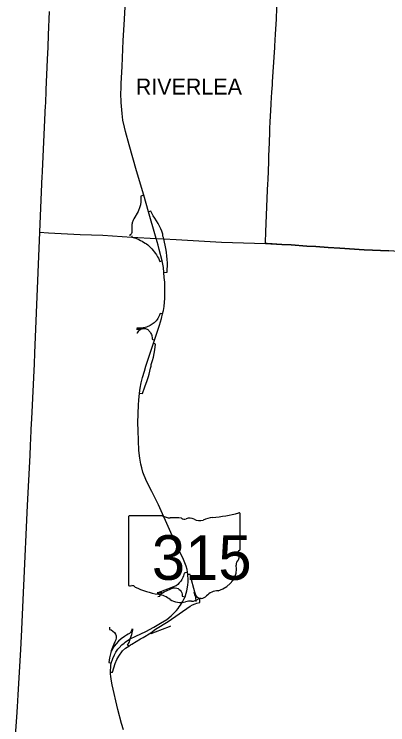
# Model space of a CAD drawing. Extents: x -1146 to -445, y -1283 to -822.
# Drawn here: x -916.9 to -887.8, y -1003.9 to -948.5 of the extents above; entities that cross this region are included whole.
import ezdxf

# ---------------------------------------------------------------- set-up
doc = ezdxf.new("R2010")
doc.units = 0
for name, color, linetype in [('GM_X_Corporation_Text', 7, 'Continuous'), ('GM_X_Interchange_Ramps', 7, 'Continuous'), ('GM_X_State_Route', 7, 'Continuous'), ('GM_X_State_Shield', 7, 'Continuous'), ('GM_X_Township', 7, 'Continuous'), ('GM_X_US_Route', 7, 'Continuous')]:
    doc.layers.add(name, color=color, linetype=linetype)

msp = doc.modelspace()

# ---------------------------------------------------------------- linework, layer by layer
at = {"layer": 'GM_X_Interchange_Ramps'}
for points in [[(-906.827, -962.643), (-907.057, -962.709), (-907.047, -962.892), (-907.043, -962.958), (-907.042, -963.03), (-907.044, -963.109), (-907.049, -963.185), (-907.056, -963.249), (-907.067, -963.323), (-907.081, -963.396), (-907.099, -963.472), (-907.117, -963.537), (-907.144, -963.62), (-907.171, -963.69), (-907.198, -963.753), (-907.233, -963.826), (-907.27, -963.896), (-907.59, -964.473), (-907.625, -964.533), (-907.656, -964.595), (-907.681, -964.654), (-907.702, -964.714), (-907.722, -964.785), (-907.737, -964.856), (-907.745, -964.913), (-907.75, -964.957), (-907.752, -964.999), (-907.761, -965.439), (-907.764, -965.536), (-907.774, -965.615), (-907.793, -965.658), (-907.83, -965.7), (-907.906, -965.731), (-907.906, -965.804)], [(-905.332, -965.842), (-905.345, -965.666), (-905.412, -965.454), (-905.487, -965.272), (-905.586, -965.06), (-905.707, -964.842), (-905.959, -964.428), (-906.082, -964.234), (-906.267, -963.893), (-906.453, -963.946)], [(-907.753, -965.807), (-907.753, -965.913), (-907.537, -965.966), (-907.447, -965.995), (-907.333, -966.038), (-907.204, -966.093), (-907.064, -966.16), (-906.95, -966.221), (-906.833, -966.291), (-906.714, -966.369), (-906.612, -966.442), (-906.516, -966.517), (-906.411, -966.607), (-906.3, -966.71), (-906.194, -966.819), (-906.09, -966.937), (-906, -967.05), (-905.904, -967.184), (-905.829, -967.3), (-905.745, -967.444), (-905.686, -967.557), (-905.575, -967.796), (-905.382, -967.753)], [(-905.258, -968.657), (-905.006, -968.637), (-904.987, -967.927), (-904.993, -967.623), (-905.014, -967.387), (-905.061, -967.077), (-905.106, -966.795), (-905.272, -966.05), (-905.297, -965.946), (-905.332, -965.842)], [(-905.359, -971.899), (-905.55, -971.859), (-905.61, -972.002), (-905.647, -972.083), (-905.685, -972.158), (-905.73, -972.242), (-905.776, -972.318), (-905.863, -972.442), (-905.943, -972.523), (-906.008, -972.581), (-906.084, -972.643), (-906.16, -972.698), (-906.245, -972.753), (-906.333, -972.802), (-906.42, -972.845), (-906.516, -972.885), (-906.615, -972.92), (-906.711, -972.948), (-906.812, -972.971), (-906.873, -972.977), (-906.972, -972.992), (-907.091, -973), (-907.215, -973.008), (-907.345, -973.01), (-907.398, -973.031)], [(-907.394, -973.085), (-907.318, -973.085), (-907.129, -973.076), (-906.942, -973.027), (-906.937, -973.045)], [(-907.362, -973.37), (-907.3, -973.367), (-907.254, -973.277), (-907.213, -973.219), (-907.164, -973.167), (-907.111, -973.124), (-907.059, -973.092), (-906.988, -973.059), (-906.937, -973.045), (-906.913, -973.038), (-906.843, -973.028), (-906.776, -973.028), (-906.695, -973.038), (-906.624, -973.059), (-906.566, -973.085), (-906.515, -973.115), (-906.465, -973.152), (-906.428, -973.187), (-906.394, -973.225), (-906.347, -973.283), (-906.302, -973.348), (-906.261, -973.422), (-906.232, -973.485), (-906.206, -973.564), (-906.188, -973.638), (-906.177, -973.724), (-906.172, -973.868), (-905.983, -973.933)], [(-906.256, -975.974), (-906.234, -975.826), (-906.139, -975.535), (-906.068, -975.262), (-906.007, -974.972), (-905.967, -974.687), (-905.897, -974.242), (-906.069, -974.183)], [(-907.155, -978.066), (-906.922, -978.104), (-906.731, -977.581), (-906.555, -977.082), (-906.446, -976.773), (-906.408, -976.597), (-906.289, -976.112), (-906.256, -975.974)], [(-903.407, -992.018), (-903.672, -992.114), (-903.719, -992.301), (-903.774, -992.449), (-903.852, -992.598), (-903.938, -992.723), (-904.054, -992.866), (-904.17, -992.979), (-904.312, -993.078), (-904.467, -993.143), (-904.628, -993.218), (-905.725, -993.625), (-905.79, -993.639)], [(-902.452, -994.306), (-902.453, -994.139), (-902.544, -994.078), (-902.641, -994.001), (-902.725, -993.895), (-902.763, -993.806), (-902.84, -993.575), (-902.914, -993.296), (-903.112, -992.611), (-903.215, -992.206), (-903.388, -992.21)], [(-905.771, -993.716), (-905.701, -993.693), (-905.391, -993.582), (-905.376, -993.636)], [(-905.734, -993.917), (-905.583, -993.901), (-905.543, -993.808), (-905.509, -993.759), (-905.44, -993.677), (-905.376, -993.636), (-905.239, -993.569), (-904.524, -993.258), (-904.377, -993.249), (-904.253, -993.272), (-904.154, -993.303), (-904.06, -993.365), (-903.991, -993.425), (-903.915, -993.527), (-903.853, -993.644), (-903.828, -993.74), (-903.825, -993.866), (-903.831, -993.897), (-903.611, -993.947)], [(-902.754, -994.32), (-902.755, -994.2), (-902.766, -994.081), (-902.78, -993.968), (-902.812, -993.863), (-902.899, -993.594), (-902.84, -993.575)], [(-909.416, -999.818), (-909.252, -999.819), (-909.043, -999.133), (-908.911, -998.824), (-908.765, -998.571), (-908.467, -998.159), (-908.254, -997.962), (-907.993, -997.784), (-907.856, -997.691), (-907.748, -997.626), (-907.079, -997.225), (-906.877, -997.115), (-906.285, -996.742), (-905.897, -996.479), (-904.922, -995.871), (-903.216, -994.684), (-903.023, -994.574), (-902.829, -994.486), (-902.691, -994.442), (-902.451, -994.393), (-902.452, -994.306)], [(-909.48, -996.311), (-909.486, -996.486), (-909.371, -996.525), (-909.23, -996.619), (-909.108, -996.73), (-909.035, -996.846), (-908.982, -996.99), (-908.984, -997.149), (-909.009, -997.298), (-909.071, -997.456), (-909.153, -997.638), (-909.254, -997.9), (-909.362, -998.16), (-909.399, -998.292), (-909.42, -998.388), (-909.485, -998.709), (-909.529, -999.067), (-909.35, -999.127)], [(-907.762, -996.436), (-907.756, -996.533), (-907.794, -996.649), (-907.851, -996.733), (-907.924, -996.799), (-908.036, -996.869), (-908.161, -996.946), (-908.323, -997.039), (-908.581, -997.222), (-908.795, -997.409), (-908.983, -997.61), (-909.126, -997.797), (-909.234, -997.976), (-909.329, -998.176), (-909.362, -998.16)], [(-907.993, -997.784), (-908.086, -997.706), (-907.968, -997.507), (-907.872, -997.232), (-907.748, -996.873), (-907.663, -996.521), (-907.669, -996.441)], [(-906.285, -996.742), (-906.25, -996.818), (-905.899, -996.666), (-904.817, -996.26), (-904.704, -996.206)]]:
    msp.add_lwpolyline(points, dxfattribs=at)
at = {"layer": 'GM_X_State_Route'}
for points in [[(-908.513, -952.597), (-908.427, -950.591), (-908.354, -949.36), (-908.249, -947.514), (-908.22, -946.809)], [(-908.584, -954.308), (-908.57, -953.942), (-908.513, -952.597)], [(-908.475, -956.542), (-908.513, -956.277), (-908.57, -955.418), (-908.599, -954.687), (-908.584, -954.308)], [(-905.9, -965.843), (-906.453, -963.946), (-906.827, -962.643), (-907.378, -960.731), (-907.964, -958.723), (-908.241, -957.667), (-908.327, -957.323), (-908.441, -956.778), (-908.475, -956.542)], [(-905.705, -966.546), (-905.851, -966.018), (-905.9, -965.843)], [(-908.412, -1004.323), (-908.549, -1003.819), (-908.852, -1002.72), (-909.284, -1000.82), (-909.362, -1000.362), (-909.399, -1000.129), (-909.409, -999.968), (-909.416, -999.818), (-909.409, -999.675), (-909.399, -999.453), (-909.376, -999.291), (-909.35, -999.127), (-909.233, -998.757), (-909.108, -998.476), (-908.986, -998.264), (-908.829, -998.026), (-908.738, -997.914), (-908.534, -997.701), (-908.361, -997.565), (-908.263, -997.487), (-908.079, -997.352), (-907.872, -997.232), (-907.433, -997.011), (-906.665, -996.649), (-906.044, -996.318), (-905.515, -996.013), (-905.026, -995.708), (-904.69, -995.42), (-904.424, -995.172), (-904.269, -995.005), (-904.138, -994.853), (-904.056, -994.728), (-903.954, -994.59), (-903.811, -994.344), (-903.701, -994.133), (-903.611, -993.947), (-903.52, -993.658), (-903.467, -993.493), (-903.414, -993.206), (-903.388, -993.021), (-903.373, -992.799), (-903.373, -992.546), (-903.384, -992.297), (-903.388, -992.21), (-903.407, -992.018), (-903.455, -991.82), (-903.529, -991.55), (-903.738, -991.033), (-904.033, -990.381), (-904.707, -988.942), (-905.685, -986.787), (-906.186, -985.748), (-906.599, -984.921), (-906.885, -984.232), (-906.985, -983.892), (-907.055, -983.605), (-907.132, -983.126), (-907.194, -982.53), (-907.264, -980.99), (-907.278, -980.382), (-907.231, -978.97), (-907.217, -978.604), (-907.155, -978.066), (-907.102, -977.681), (-907.026, -977.277), (-906.922, -976.849), (-906.774, -976.364), (-906.651, -975.959), (-906.069, -974.183), (-905.983, -973.933), (-905.592, -972.767), (-905.445, -972.24), (-905.359, -971.899), (-905.291, -971.633), (-905.232, -971.311), (-905.181, -970.671), (-905.175, -969.973), (-905.193, -969.428), (-905.225, -969.066), (-905.258, -968.657), (-905.289, -968.286), (-905.382, -967.753), (-905.614, -966.873), (-905.705, -966.546)]]:
    msp.add_lwpolyline(points, dxfattribs=at)
at = {"layer": 'GM_X_State_Shield'}
for p, q in [((-905.383, -987.622), (-907.932, -987.622)), ((-899.316, -990.254), (-899.316, -987.491)), ((-908.017, -987.712), (-908.017, -992.996)), ((-899.317, -990.254), (-899.316, -990.254))]:
    msp.add_line(p, q, dxfattribs=at)
for centre, major_axis, start_param, end_param in [((-907.917, -987.701), (0.101, 0), 1.712693, 3.28349), ((-904.777, -987.008), (0.978, 0), 4.042523, 4.731795), ((-902.416, -980.419), (9.227, 0), 4.814394, 5.042369), ((-899.413, -987.479), (0.0969, 0), 6.141152, 7.989035), ((-904.452, -990.588), (3.51, 0), 1.404758, 1.657858), ((-903.656, -987.674), (0.282, 0), 3.836095, 5.185415), ((-903.241, -988.284), (0.586, 0), 0.950623, 2.079405), ((-902.485, -987.447), (0.705, 0), 4.081561, 5.145723), ((-901.239, -989.235), (1.856, 0), 1.699011, 2.107814), ((-899.339, -990.457), (0.15, 0), 1.883978, 3.671073), ((-899.42, -990.265), (0.104, 0), 5.05454, 6.418171), ((-900.292, -990.807), (0.9, 0), 5.934695, 6.695948), ((-901.899, -991.762), (2.308, 0), 5.101752, 6.440018), ((-898.969, -991.411), (0.655, 0), 2.387724, 3.262537), ((-907.917, -993.007), (0.102, 0), 3.00124, 4.508301), ((-907.901, -992.467), (0.776, 0), 4.665946, 4.897461), ((-907.742, -993.3), (0.28, 0), 0.519207, 1.627899), ((-904.209, -988.554), (6.663, 0), 4.195997, 4.488961), ((-906.196, -995.369), (2.085, 0), 0.823519, 1.323587), ((-900.926, -994.479), (1.264, 0), 1.647645, 2.488434), ((-903.941, -993.327), (1.323, 0), 4.026481, 4.996735), ((-903.177, -995.153), (1.087, 0), 1.495662, 1.94098), ((-903.08, -993.722), (0.705, 0), 4.691044, 5.507374), ((-902.442, -994.234), (0.198, 0), 1.147584, 2.315152), ((-902.527, -993.508), (0.746, 0), 4.937069, 5.64225)]:
    msp.add_ellipse(centre, major_axis=major_axis, ratio=0.8, start_param=start_param, end_param=end_param, dxfattribs=at)
at = {"layer": 'GM_X_Township'}
for points in [[(-914.177, -948.328), (-914.254, -950.134), (-914.296, -951.093), (-914.336, -952.048), (-914.439, -954.432), (-914.484, -955.503), (-914.49, -955.625), (-914.517, -956.216), (-914.724, -960.765), (-914.741, -960.908), (-914.761, -961.127), (-914.943, -965.512), (-915.317, -974.951), (-915.358, -975.787), (-915.565, -980.074), (-915.604, -980.871), (-915.611, -981.008), (-915.666, -982.149), (-915.702, -982.896), (-915.895, -986.825), (-916.195, -993.062), (-916.363, -997.038), (-916.409, -998.056), (-916.635, -1001.582), (-916.691, -1002.532), (-916.732, -1003.331), (-916.907, -1005.839)], [(-914.943, -965.512), (-914.247, -965.562), (-911.762, -965.703), (-910, -965.75), (-907.753, -965.913), (-905.851, -966.018), (-905.272, -966.05), (-904.299, -966.104), (-900.782, -966.287), (-897.337, -966.391), (-896.065, -966.473), (-895.339, -966.52), (-894.117, -966.599), (-893.437, -966.643), (-892.459, -966.706), (-891.566, -966.763), (-889.657, -966.886), (-887.755, -966.987)]]:
    msp.add_lwpolyline(points, dxfattribs=at)
at = {"layer": 'GM_X_US_Route'}
for points in [[(-896.897, -955.529), (-896.894, -955.479), (-896.867, -955.024), (-896.842, -954.602), (-896.808, -954.026), (-896.797, -953.835), (-896.795, -953.8), (-896.746, -953.02), (-896.629, -951.135), (-896.621, -951.019), (-896.559, -950.089), (-896.481, -948.913), (-896.452, -948.041), (-896.428, -947.306), (-896.405, -946.579)], [(-897.212, -966.399), (-897.338, -966.391), (-897.341, -966.336), (-897.308, -965.496), (-897.183, -962.244), (-897.159, -961.755), (-897.147, -961.439), (-897.094, -960.027), (-897.078, -959.59), (-897.038, -958.518), (-897.008, -957.72), (-896.996, -957.419), (-896.979, -956.947), (-896.977, -956.898), (-896.953, -956.491), (-896.897, -955.537), (-896.897, -955.529)], [(-885.635, -967.115), (-885.839, -967.112), (-887.755, -966.987), (-889.657, -966.886), (-891.566, -966.763), (-892.459, -966.706), (-893.437, -966.643), (-894.117, -966.599), (-895.339, -966.52), (-896.065, -966.473), (-897.212, -966.399)]]:
    msp.add_lwpolyline(points, dxfattribs=at)

# ---------------------------------------------------------------- texts
at = {"layer": 'GM_X_Corporation_Text'}
msp.add_text('RIVERLEA', height=1.25, rotation=0, dxfattribs=at).set_placement((-907.446, -954.796))
at = {"layer": 'GM_X_State_Shield'}
msp.add_text('315', height=3.4805, dxfattribs=at).set_placement((-906.193, -992.623))

doc.saveas('drawing.dxf')
